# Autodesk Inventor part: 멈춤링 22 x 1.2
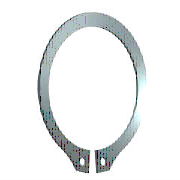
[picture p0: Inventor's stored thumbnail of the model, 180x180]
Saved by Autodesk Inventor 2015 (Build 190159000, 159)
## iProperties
IsCustomPart: 0
Created: 2015-11
Part Number: 멈춤링 22 x 1.2
Material: 스테인리스강
Description: 리테이닝 링(C형)
Document SubType Name: Modeling
Standard: KS B 1336
Designer: mdu
Standards Organization: KS
Language: ko-KR
Size Designation: 22 x 1.2
Categories: <MemberInstance><Categories><Category DisplayName="샤프트 부품" InternalName="7f7aeb1f-a693-4053-b835-cee3144e0d98" Mnemonic="SHFT"><Category DisplayName="써클립" Inter
Density: 1 g/cm^3
Appearance: 반광택
Author: mdu
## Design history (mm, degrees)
sketch "스케치1"
  geometry: L1 (-6, 0)-(6, 0) reference; L2 (0, 20.189)-(0, -80.536) reference; L3 (-48.09, 0)-(48.09, 0) reference; L4 (-0.5, -21.488)-(-0.5, -25.588); L5 (-0.5, -6.54)-(-0.5, -13.29); L6 (-2.795, 2.7)-(3.672, 2.7); L7 (0.5, -6.54)-(0.5, -13.29); L8 (0.5, -21.488)-(0.5, -25.588); C1 r 1 at (-2, -23.437); C2 r 1 at (2, -23.437); A1 r 10.5 centre (0, -11) between (0.5, -21.488) and (-0.5, -21.488); A2 r 13.025 centre (0, -10.325) between (5.149, -22.289) and (-5.149, -22.289); A3 r 14.597 centre (0, -11) between (-2.318, -25.411) and (-0.5, -25.588); A4 r 2 centre (-2, -23.437) between (-3.97, -23.781) and (-2.318, -25.411); A5 r 2 centre (-5.94, -24.126) between (-3.97, -23.781) and (-5.149, -22.289); A6 r 2 centre (5.94, -24.126) between (5.149, -22.289) and (3.97, -23.781); A7 r 2 centre (2, -23.437) between (2.318, -25.411) and (3.97, -23.781); A8 r 14.597 centre (0, -11) between (0.5, -25.588) and (2.318, -25.411)
  constraints: 16 point on circle, 12 end point, 10 centre point, 9 symmetric about line, 5 point on line, 4 tangent, 3 coincident, 2 horizontal, 1 perpendicular, 1 vertical, 5 other
  dimensions: "d0" = 21 diameter of A1 (= ND); "d1" = 4.1 distance of L4.end L4.start (= SRB2); "d6" = 0.5 distance between parallel lines of L2 L5 (= 0.25 x SD5); "d7" = 2.7 distance between parallel lines of L6 L3 (= SRB1); "d8" = 0.675 distance of A1.centre A2.centre (= 0.25 x SRB1); "d9" = 2 radius of A4 (= SD5); "d10" = 2 radius of A5 (= SD5); "d11" = 1.5 distance from line of L4 A4.centre (= 0.75 x SD5); "d12" = 2 diameter of C1 (= SD5); "d13" = 2 diameter of C2 (= SD5); "d14" = 11 distance from line of A1.centre L1 (= 0.5 x WD)
extrude "본체" new body sketch "스케치1" distance "d2" = 1.2 (= SD); taper "d3" = 0 deg
workaxis "Work Axis1"
workplane "Work Plane1"
body "Solid1"
other parameters: "WD" = 22 (= WDMIN) [user parameter; used in 1 equation term], "SD" = 1.2 [user parameter; used in 1 equation term], "SRB1" = 2.7 [user parameter; used in 2 equation terms], "ND" = 21 [user parameter; used in 1 equation term], "SRB2" = 4.1 [user parameter; used in 1 equation term], "SD5" = 2 [user parameter; used in 6 equation terms], "d15" = 0, "d16" = 0, "d17" = 0, "d41" = 0, "d42" = 0, "WDMIN" = 22 [user parameter; used in 1 equation term], "SD3" = 20.5 [user parameter], "WDMAX" = 24 [user parameter]
